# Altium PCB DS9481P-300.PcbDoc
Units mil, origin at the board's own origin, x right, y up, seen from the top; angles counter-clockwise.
Board outline 866.14 x 629.92 mil, 2 copper layers (Top Layer, Bottom Layer); 44 components, 31 nets, 174 pads, 34 vias.
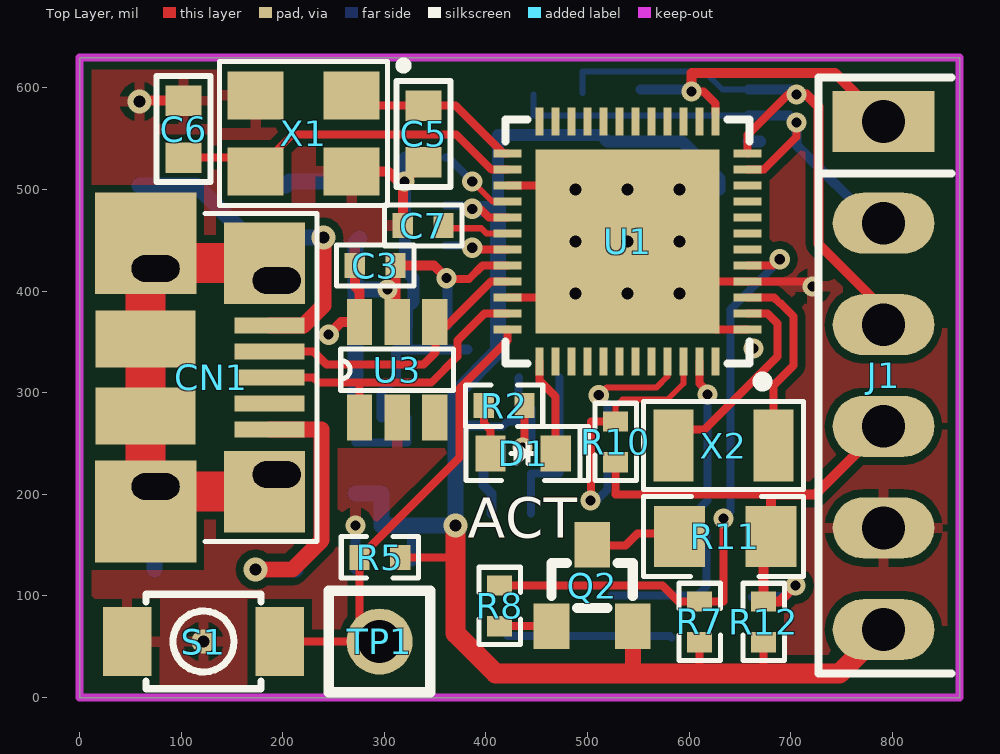
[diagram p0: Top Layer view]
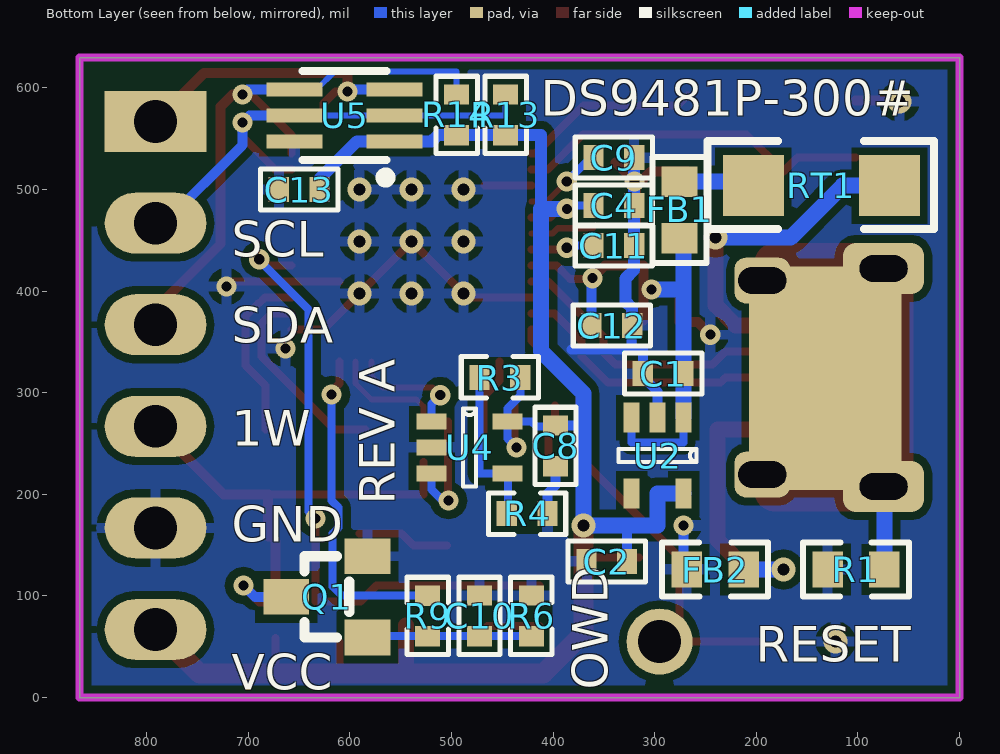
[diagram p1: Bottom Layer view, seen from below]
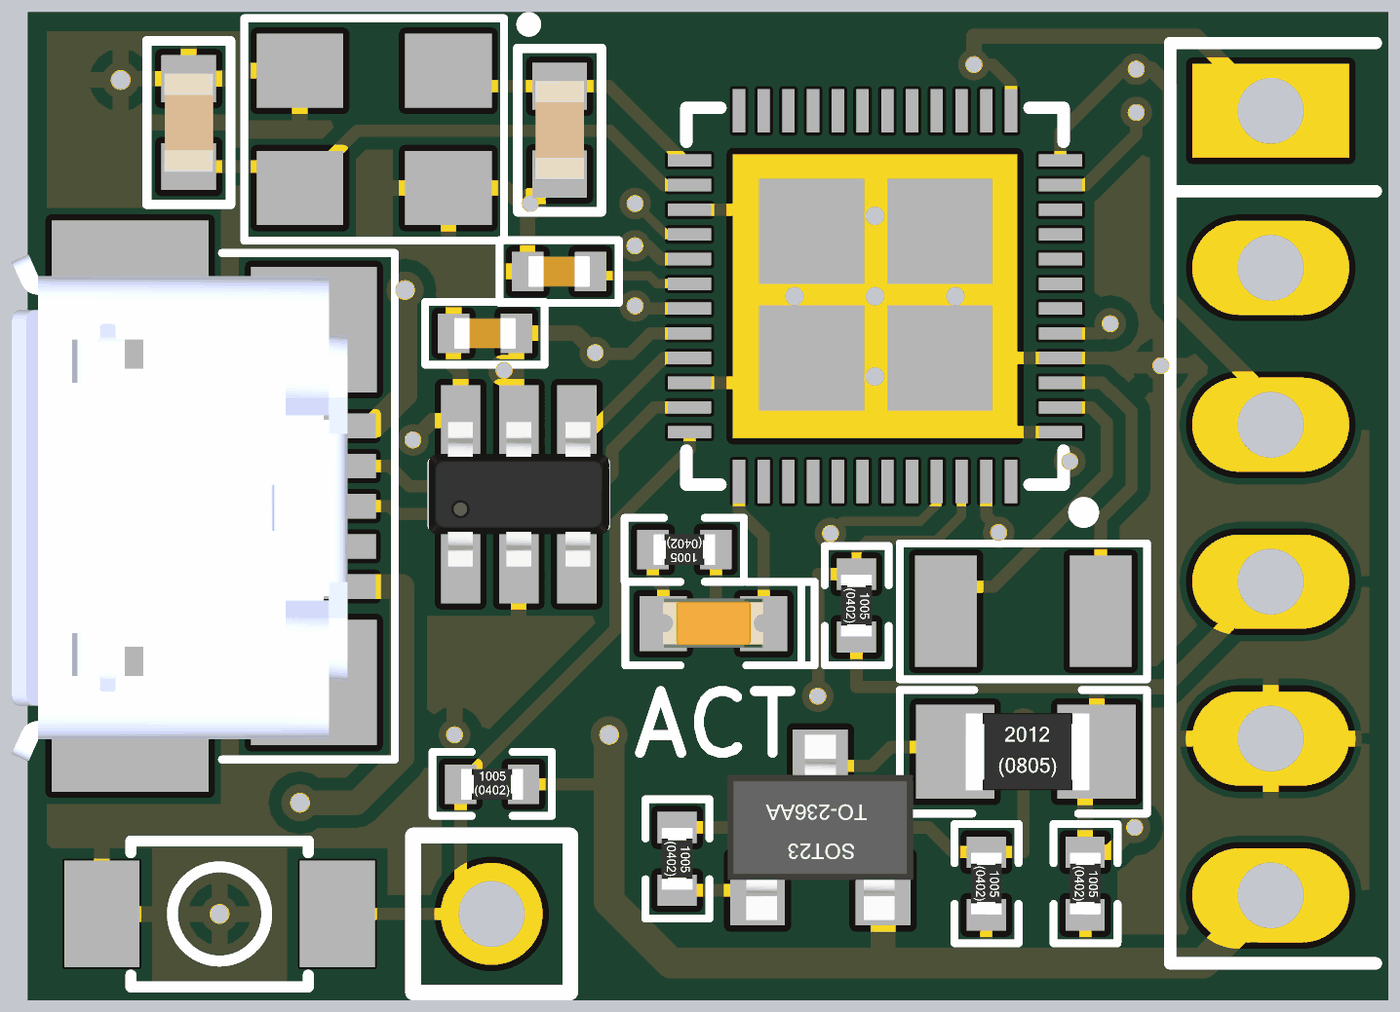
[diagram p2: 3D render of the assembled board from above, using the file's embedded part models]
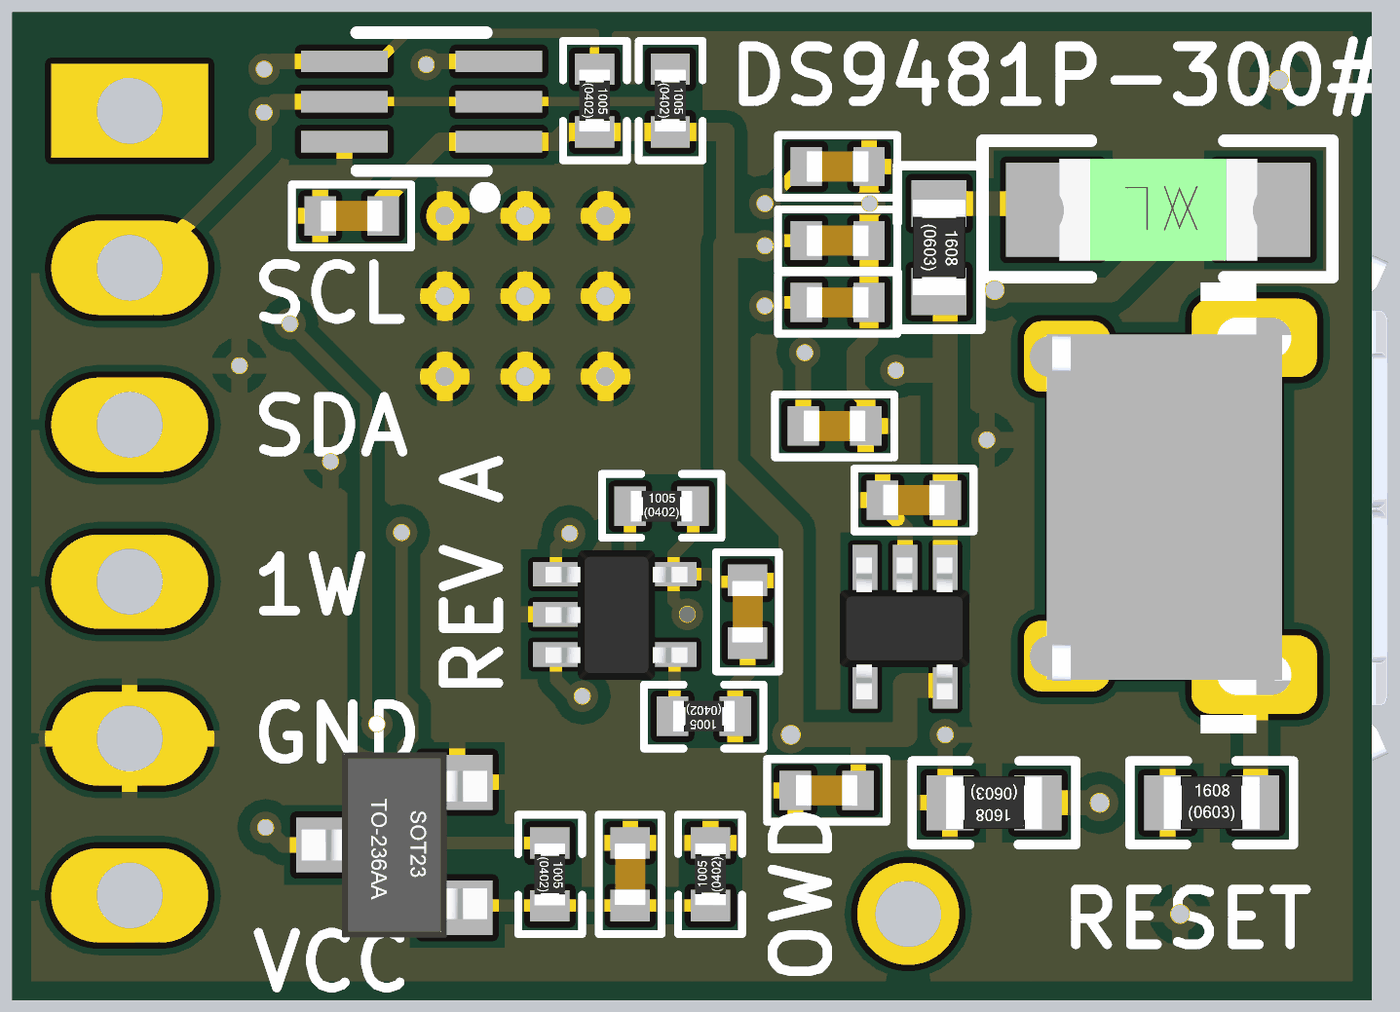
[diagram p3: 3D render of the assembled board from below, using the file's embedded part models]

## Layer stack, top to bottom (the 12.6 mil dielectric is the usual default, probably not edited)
Top Layer: signal copper 1.4
Dielectric: dielectric 12.6, FR-4, Dk 4.8
Bottom Layer: signal copper 1.4

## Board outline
0,0 866.14,0 866.14,629.92 0,629.92

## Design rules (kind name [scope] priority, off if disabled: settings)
Clearance PolygonClearance [InPolygon] p1: gap=7.87
Clearance [All] p2: gap=6
DiffPairsRouting [All] p1: maxlimit=10 minlimit=10 mostfreqgap=10 maxuncoupledlength=500
HoleToHoleClearance [All] p1: gap=7.87 allowstackedmicrovias=TRUE
MinimumAnnularRing [All] p1: minimumring=5
MinimumSolderMaskSliver [All] p1: minsoldermaskwidth=3
PolygonConnect [All] p1: connectstyle=Relief reliefconductorwidth=10 reliefentries=4 polygonreliefangle="90 Angle"
RoomDefinition DS9481P-300 [InComponentClass('DS9481P-300')] p1: confinementstyle=ConfineIn formatcopy=TRUE lockcomponents=FALSE outline -114.17,-94.49 976.38,-94.49 976.38,724.41 -114.17,724.41
RoutingVias [All] p1: holewidth=11.81 width=23.62 viastyle="Through Hole" minholewidth=10 minwidth=20.08 maxholewidth=28 maxwidth=50
SilkToSilkClearance [All] p1: silktosilkclearance=5
SilkscreenOverComponentPads [All] p1: minsilkscreentomaskgap=4
SolderMaskExpansion [All] p1: expansion=4
Width POWER_NETS_Width [InNetClass('POWER_NETS')] p1: maxlimit=39.37 minlimit=7.87 preferedwidth=19.68
Width [All] p2: maxlimit=39.37 minlimit=6 preferedwidth=7.87
23 further rules are at their usual default settings.

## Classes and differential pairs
net class POWER_NETS: VCC3.3 VCC5.0
differential pair USB: +USB_P -USB_N

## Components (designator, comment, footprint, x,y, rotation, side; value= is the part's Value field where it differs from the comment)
C1 "1uF" CAP0402-3D 271.65,318.9 r0 bottom
C2 "1uF" CAP0402-3D 327.2,133.87 r0 bottom
C3 "0.1uF" CAP0402-3D 311.02,425.2 r180 top
C4 "1uF" CAP0402-3D 360.24,484.25 r180 bottom
C5 "10pF" CAP0603-3D 338.58,582.68 r270 top
C6 "10pF" CAP0603-3D 102.36,531.5 r90 top
C7 "1uF" CAP0402-3D 358.27,464.57 r180 top
C8 "0.1uF" CAP0402-3D 397.64,267.72 r270 bottom
C9 "1uF" CAP0402-3D 360.24,531.5 r180 bottom
C10 "10pF" CAP0402-3D 472.44,100.39 r270 bottom
C11 "1uF" CAP0402-3D 360.24,444.88 r180 bottom
C12 "1uF" CAP0402-3D 362.2,366.14 r180 bottom
C13 "0.1uF" CAP0402-3D 629.92,500 r0 bottom
CN1 "USB Micro B" USBMICROB-3D 7.87,314.96 r270 top
D1 "ACT" 0603LED-3DORANGE 468.5,240.16 r180 top
FB1 "" 0603-3D 275.59,507.87 r270 bottom
FB2 "" 0603-3D 212.6,125.98 r0 bottom
J1 "PMOD Output" SIP6-SOCKET2-RA-3D 791.34,566.93 r270 top
Q1 "2N7002" 16001-3D 582.68,59.06 r270 bottom
Q2 "PMV65XP" 16001-3D 464.57,70.24 r180 top
R1 "10" 0603-3D 129.92,125.98 r180 bottom
R2 "1.5k" 0402-3D 437.99,287.4 r180 top
R3 "100K" 0402-3D 472.44,314.96 r180 bottom
R4 "32.4K/1%" 0402-3D 405.51,181.1 r0 bottom
R5 "4.7k" 0402-3D 275.59,137.8 r0 top
R6 "100k" 0402-3D 421.26,100.39 r270 bottom
R7 "100k" 0402-3D 610.24,94.49 r270 top
R8 "1k" 0402-3D 413.39,110.24 r270 top
R9 "2.2k" 0402-3D 523.62,60.31 r90 bottom
R10 "499" 0402-3D 527.56,271.65 r270 top
R11 "4.99" 0805-3D 590.55,158.46 r0 top
R12 "680" 0402-3D 673.23,94.49 r270 top
R13 "1.74k" 0402-3D 446.85,593.5 r270 bottom
R14 "1.74k" 0402-3D 495.08,593.5 r270 bottom
RT1 "PTC Fuse MF-NSMF012-2" 1206POLYFUSE-3D 68.9,503.94 r0 bottom
S1 "RESET" RESET9-3d 122.05,55.12 r0 top
TP1 "OWD" SIP1 295.28,55.12 r180 top
U1 "MAXQ1010-A01+" "TQFN48 6MM" 539.37,448.82 r180 top
U2 "MAX8891" SC70-5-3D 271.65,275.59 r270 bottom
U3 "MAX3207" sot23-6-3D 275.59,275.59 r90 top
U4 "MAX9140" SC70-5-3D 519.69,271.65 r180 bottom
U5 "MAX13204E" "TDFN6 2MM .65" 552.17,547.24 r0 bottom
X1 "12 MHz Crystal" FA-238V 220.47,555.12 r180 top
X2 "DNP" M8 633.86,248.03 r180 top

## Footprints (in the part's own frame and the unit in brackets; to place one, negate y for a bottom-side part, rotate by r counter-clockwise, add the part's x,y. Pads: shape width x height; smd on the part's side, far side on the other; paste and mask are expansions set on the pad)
0402-3D [mil]
  rect 20x25 smd: 1(0,0) 2(40,0)
  silkscreen extent -18,-20 58,21, body extent 0,-10 40,10, height 14
0603-3D [mil]
  rect 30x35 smd: 1(0,0) 2(56,0)
  silkscreen extent -24,-27 80,27, body extent -3,-17 59,17, height 18
0603LED-3DORANGE [mil]
  rect 30x35 smd: 1(0,0) 2(64,0)
  silkscreen extent -32,-27 88,27, body extent 0,-16 64,15, height 24
0805-3D [mil]
  rect 50x60 smd: 1(0,0) 2(90,0)
  silkscreen extent -35,-39 122,39, body extent 7,-25 85,25, height 18
1206POLYFUSE-3D [mil]
  rect 60x60 smd: 1(0,0) 2(134,0)
  silkscreen extent -44,-44 179,43, body extent 4,-33 130,33, height 22
16001-3D [mil]
  rect 35x45 smd: 1(0,0) 2(-80,0) 3(-40,-80)
  silkscreen extent -80,-62 0,-18, body extent -99,-99 19,19, height 51
CAP0402-3D [mil]
  rect 20x25 smd: 1(0,0) 2(40,0)
  silkscreen extent -18,-20 58,20, body extent 0,-10 40,10, height 23
CAP0603-3D [mil]
  rect 30x35 smd: 1(0,0) 2(56,0)
  silkscreen extent -24,-27 80,27, body extent -3,-16 59,16, height 31
FA-238V [mm] "Seiko Epson FA-238V Crystal"
  rect 1.4x1.2 smd paste+0: 1(-1.2,-0.95)
  rect 1.4x1.2 smd: 2(1.2,-0.95) 3(1.2,0.95) 4(-1.2,0.95)
  silkscreen extent -2.1,-1.8 2.1,1.8, body extent -1.6,-1.25 1.6,1.25, height 0.7
M8 [mm] "Hong Kong X'tals M8 Crystal"
  rect 1x1.8 smd: 1(-1.25,0) 2(1.25,0)
  silkscreen extent -2,-1.1 2,1.1
RESET9-3d [mil]
  rect 48x68 smd mask+1.18: 1(-75,0) 2(75,0)
  silkscreen extent -57,-47 56,46, body extent -80,-50 80,50, height 66
SC70-5-3D [mm]
  rect 0.75x0.4 smd mask+0.076: 1(0,0) 2(0,-0.65) 3(0,-1.3) 4(1.9,-1.3) 5(1.9,0)
  silkscreen extent 0.79,-1.62 1.11,0.33, body extent -0.17,-1.71 2.13,0.39, height 1
SIP1 [mil]
  round 65 hole 42: 1(0,0)
  silkscreen extent -50,-50 50,50
SIP6-SOCKET2-RA-3D [mil]
  rect 60x100 hole 42: 1(0,0)
  oval 60x100 hole 42: 2(100,0) 3(200,0) 4(300,0) 5(400,0) 6(500,0)
  body extent -51,-12 551,169, height 100
sot23-6-3D [mil]
  rect 45x25 smd: 1(0,0) 2(0,-37) 3(0,-74) 4(94,-74) 5(94,-37) 6(94,0)
  silkscreen extent 26,-92 68,19, body extent 1,-94 93,20, height 39
"TDFN6 2MM .65" [mm]
  rect 1.4x0.35 smd: 1(0.1,0) 2(0.1,-0.65) 3(0.1,-1.3) 4(2.6,-1.3) 5(2.6,-0.65) 6(2.6,0)
  silkscreen extent 0.2,-1.77 2.4,1.02, body extent 0.33,-1.67 2.37,0.38, height 0.8
"TQFN48 6MM" [mm] "48Pin 6x6mm Body 0.4mm pitch"
  rect 0.7x0.2 smd mask+0.051: 1(-3,2.2) 2(-3,1.8) 3(-3,1.4) 4(-3,1) 5(-3,0.6) 6(-3,0.2) 7(-3,-0.2) 8(-3,-0.6) 9(-3,-1) 10(-3,-1.4) 11(-3,-1.8) 12(-3,-2.2) 25(3,-2.2) 26(3,-1.8) 27(3,-1.4) 28(3,-1) 29(3,-0.6) 30(3,-0.2) 31(3,0.2) 32(3,0.6) 33(3,1) 34(3,1.4) 35(3,1.8) 36(3,2.2)
  rect 0.2x0.7 smd mask+0.051: 13(-2.2,-3) 14(-1.8,-3) 15(-1.4,-3) 16(-1,-3) 17(-0.6,-3) 18(-0.2,-3) 19(0.2,-3) 20(0.6,-3) 21(1,-3) 22(1.4,-3) 23(1.8,-3) 24(2.2,-3) 37(2.2,3) 38(1.8,3) 39(1.4,3) 40(1,3) 41(0.6,3) 42(0.2,3) 43(-0.2,3) 44(-0.6,3) 45(-1,3) 46(-1.4,3) 47(-1.8,3) 48(-2.2,3)
  rect 4.6x4.6 smd paste-5: EP(0,0)
  silkscreen extent -3.5,-3.05 3.05,3.62, body extent -3.05,-3.05 3.05,3.05, height 0.8
USBMICROB-3D [mm]
  rect 0.4x1.75 smd mask+0.076: 1(-1.3,4.555) 2(-0.65,4.555) 3(0,4.555) 4(0.65,4.555) 5(1.3,4.555)
  rrect50% 1.143x1.397 hole 0.66 slot 1.2 at 90 deg: 6(2.425,4.73) 9(-2.425,4.73)
  rrect50% 1.27x2.032 hole 0.66 slot 1.2 at 90 deg: 7(2.725,1.7) 8(-2.725,1.7)
  rect 2.032x2.032 smd: 10(-2.86,4.425) 11(2.855,4.425)
  rect 2.54x2.54 smd: 12(3.35,1.453) 15(-3.355,1.453)
  rect 1.43x2.5 smd: 13(0.96,1.45) 14(-0.96,1.45)
  rect 5.588x3.81 smd far side mask+0.03: 16(0.013,3.155)
  silkscreen extent -4.1,2.94 4.1,5.73, body extent -4.07,-0.46 4.13,4.97, height 2.62

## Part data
C1 C2 C4 C7 C9 C11 C12: library part CAP, "CAP CER 1UF 6.3V 20% X5R 0402"
C3 C8 C13: library part CAP, "CAP CER 0.1UF 6.3V 10% X5R 0402"
C5 C6: library part CAP, "CAP CER 10PF 50V C0G 0603"
C10: library part CAP, "CAP CER 10PF 50V 5% NP0 0402"
CN1: library part USB-MICRO-B, "CONN RCPT STD MICRO USB TYPE B"
D1: library part LED, "LED ORANGE HIGH BRIGHT USS 0603"
FB1 FB2: library part FUSE1, "FERRITE CHIP 220 OHM 2200MA 0603"
J1: library part CON6, "CONN RCPT .100\" 6POS R/A SGL TIN"
Q1: library part "NCHAN FET", "N MOSFET - 2N7002"
Q2: library part "PCHAN FET", "P-MOSFET - PMV65XP"
R1: library part RESISTOR, "RES SMD 10 OHM 5% 1/10W 0603"
R2: library part RESISTOR, "RES SMD 1.5K OHM 5% 1/16W 0402"
R3 R6 R7: library part RESISTOR, "RES SMD 100K OHM 1% 1/16W 0402"
R4: library part RESISTOR, "RES SMD 32.4K OHM 1% 1/16W 0402"
R5: library part RESISTOR, "RES SMD 4.7K OHM 5% 1/10W 0402"
R8: library part RESISTOR, "RES SMD 1K OHM 5% 1/16W 0402"
R9: library part RESISTOR, "RES SMD 2.2K OHM 5% 1/10W 0402"
R10: library part RESISTOR, "RES SMD 499 OHM 1% 1/16W 0402"
R11: library part RESISTOR, "RES SMD 4.99 OHM 1% 1/8W 0805"
R12: library part RESISTOR, "RES SMD 680 OHM 5% 1/10W 0402"
R13 R14: library part RESISTOR, "RES SMD 1.74K OHM 1% 1/10W 0402"
RT1: library part THERMISTOR, "PTC Fuse 1206"
S1: library part SW-PB, "SWITCH TACTILE SPST-NO 0.05A 12V"
TP1: library part TP, "CONN HEADER 1POS .100 VERT GOLD"
U1: library part MAXQ1010, "Security Token Microcontroller with RTC and USB"
U2: "High PSRR, Low-Dropout, 150mA  Linear Regulator"
U3: library part MAX3207E, "Dual High-Speed  Differential ESD-Protection IC"
U4: library part OPAMP, "40ns Single-Supply Comparator"
U5: library part MAX13204, "4 Channel +/- 30kv ESD Protector"
X1: library part CRYSTAL3, "CRYSTAL 12MHZ 10PF SMD"
X2: library part CRYSTAL, "Do Not Populate"

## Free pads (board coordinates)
  round 10 hole 10 mask+0: 2(2240.16,19.68)
  round 11.81 hole 11.81 mask+0: 5(2240.16,-141.73)
  round 0 hole 25.98 slot 47.24 at 0 deg mask+0: ""(2240.16,-456.69)
  round 42 hole 42 mask+0: ""(2240.16,-295.28)

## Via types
v1: diameter 20.08, hole 10, Top Layer to Bottom Layer, tented both sides, 20 vias
v2: diameter 23.62, hole 11.81, Top Layer to Bottom Layer, 9 vias
v3: diameter 23.62, hole 11.81, Top Layer to Bottom Layer, tented both sides, 5 vias

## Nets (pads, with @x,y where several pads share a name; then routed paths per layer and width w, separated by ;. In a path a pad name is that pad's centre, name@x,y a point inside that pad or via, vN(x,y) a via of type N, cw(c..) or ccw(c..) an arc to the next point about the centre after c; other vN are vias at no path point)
1-WIRE: J1.4 Q1.3 R10.2 R11.2 R12.1 | length 519
  Top Layer w7.87: R10.2 527.56,199.8 680.12,199.8
  Top Layer w9.84: 680.12,199.8 724.21,199.8 J1.4 ; R11.2 R11.2@680.55,161.42 ; 680.55,199.37 R11.2@680.55,161.42 ; v1(704.72,110.24) 688.98,94.49 R12.1 673.23,154.09 R11.2@680.55,161.42
  Bottom Layer w9.84: Q1.3 693.54,99.06 v1(704.72,110.24)
1-WIRE_DRIVE: R9.2 U1.47 | length 327
  Top Layer w7.87: U1.47 610.24,309.06 618.11,301.18 v1(618.11,298.23)
  Bottom Layer w7.87: R9.2 608.05,100.31 616.99,109.25 616.99,161.56 611.22,167.32 611.22,187.01 618.11,193.9 v1(618.11,298.23)
1-WIRE_SENSE: R10.1 U1.46 U4.3 | length 252.7
  Top Layer w6: R10.1 527.56,286.42 534.45,293.31 578.74,293.31 594.49,309.06 U1.46
  Top Layer w7.87: v1@503.25,192.91 503.25,271.65 R10.1
  Bottom Layer w7.87: v1(502.95,193.9) 508.86,193.9 519.69,204.73 U4.3
EDGE_DET: U1.45 U4.1 | length 119.5
  Top Layer w6: v1(511.06,297.62) 518.74,305.31 568.03,305.31 578.74,316.01 U1.45
  Bottom Layer w7.87: v1(511.06,297.62) 519.69,288.99 U4.1
GND: C1.2 C2.2 C3.2 C4.2 C5.2 C6.2 C7.2 C8.2 C9.2 C10.1 C11.2 C12.2 C13.2 FB2.2 J1.5 Q1.2 R1.1 R4.1 R6.1 S1.1 U1.1 U1.4 U1.27 U1.34 U1.EP U2.2 U3.2 U3.6 U4.2 U5.6 X1.2 X1.4 | length 1166.4
  Top Layer w7.87: U1.34 484.25,393.7 v2(488.19,397.64) v2(539.37,448.82) v2(590.55,397.64) 625.98,362.2 U1.1 ; U1.27 U1.EP@467.52,503.94 ; U1.EP@484.33,504.01 U1.EP@488.19,507.87 ; U1.EP@610.24,409.45 U1.4 690.21,409.45 716.54,409.45 v1(721.46,404.53) v1@721.46,404.59
  Top Layer w9.84: v3@59.06,587.5 C6.2 ; v1(245.16,357.2) 257.54,369.59 U3.6 275.59,399.96 271.02,404.53 C3.2 ; X1.4 303.86,517.72 v1@318.27,503.31 ; C7.2 v1@318.27,503.31 ; C5.2 318.9,506.99 318.9,503.94 v1@318.27,503.31
  Bottom Layer w9.84: FB2.2@271.65,125.98 v1(271.65,169.29) ; U2.2 297.24,301.18 311.65,315.59 C1.2 311.65,342.52 322.83,342.52 ; C12.2@322.83,366.14 322.83,342.52 ; 381.89,342.52 322.83,342.52 ; C8.2 397.64,208.66 405.51,200.79 R4.1
  Bottom Layer w11.81: C9.2 C4.2 C11.2 320.24,420.91 328.74,412.4 328.74,389.76 322.2,383.23 C12.2 ; U5.6@658.46,547.24 U5.6@669.92,547.24
  other v1: 663.39,343.5 319.88,507.87
  other v2: 539.37,397.64 488.19,448.82 590.55,448.82 488.19,500 539.37,500 590.55,500
  other v3: 122.05,55.12 59.06,586.61
GND_EARTH: CN1.6 CN1.7 CN1.8 CN1.9 CN1.10 CN1.11 CN1.12 CN1.13 CN1.14 CN1.15 CN1.16 R1.2 | length 535.5
  Top Layer w39.37: CN1.11 70.19,202.56 65.07,207.68 65.07,352.76 65.07,422.24 70.39,427.56 CN1.10
  Bottom Layer w15.75: R1.2 73.92,207.68 CN1.7
GPIO: J1.1 U1.13 U5.3 | length 316.1
  Top Layer w7.87: v1(602.36,596.46) 614.17,596.46 625.98,584.65 U1.13@625.98,574.8
  Top Layer w9.84: v1(602.36,596.46) 602.36,614.5 743.77,614.5 J1.1
  Bottom Layer w7.87: v1@600.39,598.43 v1(602.36,596.46)
  Bottom Layer w9.84: U5.3@552.17,598.43 v1@600.39,598.43
N_1-WIRE_DPU: R7.1 R8.1 U1.5 | length 621.9
  Top Layer w7.87: R8.1 573.71,110.24 589.46,94.49 633.86,94.49 v1(633.86,176.18) ; U1.5 683.07,425.2 v1(689.17,431.3)
  Bottom Layer w7.87: v1(633.86,176.18) 640.75,183.07 640.75,381.89 689.96,431.1 689.37,431.1 v1(689.17,431.3)
NetC5_1: C5.1 U1.25 X1.1 | length 177.2
  Top Layer w7.87: X1.1 277.56,582.68 C5.1 370.08,582.68 417.36,535.4 U1.25
NetC6_1: C6.1 U1.26 X1.3 | length 354.2
  Top Layer w7.87: C6.1 159.45,531.5 X1.3 209.88,554.37 370.5,554.37 405.37,519.5 U1.26@421.26,519.5
NetC7_1: C7.1 U1.30 | length 66.2
  Top Layer w6: C7.1 360.98,461.85 395.38,461.85 400.41,456.82 U1.30@421.26,456.82
NetC9_1: C9.1 U1.28 | length 79
  Top Layer w6: v1(386.61,507.87) 406.3,488.19 U1.28
  Bottom Layer w7.87: C9.1 362.99,531.5 v1(386.61,507.87)
NetC10_2: C10.2 Q1.1 R6.2 R9.1 | length 162
  Bottom Layer w7.87: R6.2 523.62,60.39 581.34,60.39 Q1.1
NetC11_1: C11.1 U1.31 | length 62.7
  Top Layer w7.87: v1(386.61,442.61) 388.28,440.94 U1.31
  Bottom Layer w7.87: C11.1 384.35,444.88 v1(386.61,442.61)
NetCN1_1: CN1.1 RT1.1 | length 330.2
  Top Layer w15.75: CN1.1 220.28,366.14 240.16,386.02 v3(240.16,452.76)
  Bottom Layer w15.75: RT1.1@59.06,503.94 115.16,503.94 166.34,452.76 v3(240.16,452.76)
NetCN1_5: CN1.5 FB2.1 | length 276.2
  Top Layer w15.75: v3(173.23,125.98) 209.31,125.98 238.19,154.87 238.19,263.78 CN1.5
  Bottom Layer w15.75: v3(173.23,125.98) FB2.1
NetD1_1: D1.1 U1.37 | length 97.1
  Top Layer w7.87: U1.37 452.76,312.01 468.5,296.26 D1.1
NetD1_2: D1.2 R2.2 | length 49.9
  Top Layer w7.87: R2.2 397.99,269.86 404.5,263.35 D1.2
NetFB1_1: FB1.1 RT1.2 | length 74.3
  Bottom Layer w15.75: RT1.2 206.83,507.87 FB1.1
NetQ2_1: Q2.1 R8.2 | length 51.2
  Top Layer w7.87: R8.2 Q2.1
NetQ2_3: Q2.3 R11.1 | length 90.9
  Top Layer w7.87: Q2.3@504.57,149.61 537.48,149.61 549.29,161.42 R11.1@590.55,161.42
NetR3_1: R3.1 R4.2 U4.4 | length 162
  Bottom Layer w7.87: R4.2@444.25,181.1 444.25,220.47 U4.4 472.44,220.47 R3.1
NetU1_2: U1.2 X2.2 | length 198.2
  Top Layer w7.87: X2.2@584.65,263.78 615.16,263.78 687.01,335.63 687.01,368.11 677.17,377.95 U1.2
NetU1_3: U1.3 X2.1 | length 172.5
  Top Layer w7.87: U1.3 683.69,393.7 689.79,387.6 690.36,387.6 702.76,375.2 702.76,326.77 683.07,307.09 X2.1@683.07,263.78
OWD_NRST: R5.1 S1.2 TP1.1 U1.36 | length 490.5
  Top Layer w7.87: S1.2 TP1.1 ; TP1.1@307.09,66.93 TP1.1 ; U1.36 421.26,351.4 374.02,304.15 374.02,236.22 R5.1 275.59,74.8 TP1.1
SCL: J1.2 R13.1 U1.11 U5.2 U5.5 | length 499.3
  Top Layer w7.87: U1.11@657.63,519.83 U1.11 673.5,519.69 705.71,551.89 v1(705.71,565.94)
  Bottom Layer w6: R13.1 446.85,572.83 552.17,572.83 U5.5@658.46,572.83
  Bottom Layer w7.87: v1@704.72,564.96 v1(705.71,565.94)
  Bottom Layer w9.84: U5.5@658.46,572.83 698.82,572.83 v1(705.71,565.94) 705.71,543.65 782.43,466.93 J1.2
SDA: J1.3 R14.1 U1.12 U5.4 | length 592.1
  Top Layer w7.87: U1.12 657.48,553.52 697.46,593.5 v1(705.71,593.5)
  Top Layer w9.84: v1(705.71,593.5) 715.35,593.5 727.36,581.5 727.36,446.49 791.34,382.51 J1.3
  Bottom Layer w6: R14.1@495.08,594.84 495.08,616.28 615.02,616.28 632.87,598.43 U5.4@658.46,598.43
  Bottom Layer w9.84: U5.4@658.46,598.43 700.79,598.43 v1(705.71,593.5)
USB_N: CN1.2 U1.33 U3.4 | length 282.2
  Top Layer w7.87: CN1.2 230.31,340.55 243.09,327.78 338.69,327.78 350.39,339.48 350.39,354.88 404.96,409.45 U1.33
USB_P: CN1.3 U1.35 U3.1 | length 307.7
  Top Layer w7.87: CN1.3 230.32,314.96 235.37,309.9 275.59,309.9 ; U3.1 275.59,309.9 ; U1.35 398.74,377.95 372.05,351.26 372.05,335.82 346.13,309.9 275.59,309.9
VCC3.3: C2.1 C4.1 C8.1 C13.1 J1.6 Q2.2 R2.1 R3.2 R5.2 R7.2 R12.2 R13.2 R14.2 U1.29 U2.5 U4.5 U5.1 | length 1829.6
  Top Layer w7.87: R5.2 370.08,137.8 ; v1(386.47,480.95) 394.58,480.95 403.09,472.44 U1.29 ; v1(436.02,246.06) 437.99,248.03 R2.1 ; 610.24,23.84 R7.2 ; 673.23,23.84 R12.2 R12.2@673.23,58.43
  Top Layer w15.75: 544.57,23.84 Q2.2 Q2.2@544.57,70.87
  Top Layer w19.68: v3(370.08,169.29) 370.08,137.8 370.08,63.21 409.45,23.84 544.57,23.84 610.24,23.84 673.23,23.84 748.25,23.84 J1.6
  Bottom Layer w7.87: C4.1 383.17,484.25 v1(386.47,480.95) ; v3@362.2,169.29 v3(370.08,169.29) ; C8.1 398.43,266.93 416.53,266.93 421.26,271.65 U4.5 ; R3.2 432.09,314.61 432.09,297.24 444.88,284.45 U4.5 ; v1(436.02,246.06) 444.88,254.92 U4.5
  Bottom Layer w9.84: C2.1 327.2,169.29 ; 370.08,267.72 C8.1
  Bottom Layer w11.81: 411.71,480.95 411.71,553.5 R13.2 R14.2 513.43,553.5 519.68,547.24 U5.1 593.23,547.24 629.92,510.55 C13.1
  Bottom Layer w15.75: U2.5 297.24,200.79 297.24,169.29 326.77,169.29 ; 327.2,169.29 v3@362.2,169.29 ; v3(370.08,169.29) 370.08,267.72 370.08,299.21 411.71,340.84 411.71,480.95 v1(386.47,480.95)
VCC5.0: C1.1 C3.1 C12.1 FB1.2 U1.32 U2.1 U2.3 U3.5 | length 542.2
  Top Layer w7.87: U3.5@311.02,371.16 U3.5 ; v1@361.9,412.16 383.56,412.16 396.54,425.14 U1.32@421.26,425.14
  Top Layer w9.84: v1(303.15,401.57) v1@311.02,401.57 ; U3.5@311.02,371.16 v1@311.02,401.57 ; v1@361.9,412.16 v1(361.22,412.84) 348.86,425.2 C3.1 v1@311.02,401.57
  Bottom Layer w7.87: U2.1 271.65,250.89 322.83,250.89 U2.3
  Bottom Layer w9.84: v1(361.22,412.84) 362.2,411.85 C12.1
  Bottom Layer w15.75: U2.1 C1.1 271.65,401.57 ; FB1.2 271.65,447.94 271.65,401.57 ; v1(303.15,401.57) 271.65,401.57
pads on no net: CN1.4 U1.6 U1.7 U1.8 U1.9 U1.10 U1.14 U1.15 U1.16 U1.17 U1.18 U1.19 U1.20 U1.21 U1.22 U1.23 U1.24 U1.38 U1.39 U1.40 U1.41 U1.42 U1.43 U1.44 U1.48 U2.4 U3.3

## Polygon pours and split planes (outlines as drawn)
GND on Bottom Layer "Bottom Layer GND" (solid, remove dead copper, pour order 6): 0,0 866.14,0 866.14,629.92 0,629.92
GND on Top Layer "Top Layer GND" (solid, remove dead copper, pour order 5): 0,0 866.14,0 866.14,629.92 0,629.92

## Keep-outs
Keep-Out Layer:
  the board outline again, w7.87

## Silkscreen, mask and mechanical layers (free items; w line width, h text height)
Top Overlay:
  circle w7.87: c318.9,622.05 r3.94
  lines w7.87: 727.36,515.75 858.27,515.75 ; 858.27,23.62 727.36,23.62 727.36,610.24 858.27,610.24
Bottom Overlay:
  text "DS9481P-300#" at 412.4,572.83 h35
  text "SCL" at 716.46,434.06 h35
  text "SDA" at 716.46,349.41 h35
  text "1W" at 716.54,248.03 h35
  text "REV A" at 556.1,189.96 h35 r270
  text "GND" at 716.54,153.54 h35
  text "VCC" at 716.54,7.87 h35
Top Paste:
  rectangle: 465.55,375.98 532.48,442.91
  rectangle: 465.55,456.69 532.48,523.62
  rectangle: 547.24,375.98 614.17,442.91
  rectangle: 547.24,456.69 614.17,523.62
Mechanical 15:
  circle w11.81: c275.59,322.83 r3.94
  circle w11.81: c657.48,346.46 r3.94
  lines w5: 720.47,515.75 858.27,515.75 ; 379.92,267.72 379.92,308.07 455.71,308.07 455.71,267.72 379.92,267.72 ; 379.92,267.72 492.13,267.72 ; 379.92,267.72 379.92,212.6 492.13,212.6 ; 492.13,212.6 492.13,267.72 ; 492.13,212.6 500.98,212.6 500.98,267.72 492.13,267.72 ; 7.87,153.54 232.28,153.54 232.28,476.38 7.87,476.38 7.87,153.54 ; 15.75,7.87 228.35,7.87 228.35,102.36 15.75,102.36 15.75,7.87 ; 74.8,507.87 129.92,507.87 129.92,610.24 74.8,610.24 74.8,507.87 ; 252.95,405.51 295.28,405.51 328.74,405.51 328.74,444.88 252.95,444.88 252.95,405.51 ; 255.91,118.11 334.65,118.11 334.65,157.48 255.91,157.48 255.91,118.11 ; 259.84,248.03 366.14,248.03 366.14,397.64 259.84,397.64 259.84,248.03 ; 300.39,444.88 375.98,444.88 375.98,484.25 300.39,484.25 300.39,444.88 ; 311.02,503.94 366.14,503.94 366.14,606.3 311.02,606.3 311.02,503.94 ; 393.7,51.18 433.07,51.18 433.07,129.92 393.7,129.92 393.7,51.18 ; 440.94,43.31 440.94,102.36 460.63,102.36 460.63,177.17 547.24,177.17 547.24,98.43 566.93,98.43 566.93,43.31 440.94,43.31 ; 507.87,212.6 547.24,212.6 547.24,291.34 507.87,291.34 507.87,212.6 ; 555.12,122.05 712.6,122.05 712.6,200.79 555.12,200.79 555.12,122.05 ; 590.55,35.43 629.92,35.43 629.92,114.17 590.55,114.17 590.55,35.43 ; 653.54,35.43 692.91,35.43 692.91,114.17 653.54,114.17 653.54,35.43 ; 720.47,23.62 862.2,23.62 862.2,610.24 720.47,610.24 720.47,23.62
  text "TOP ASSEMBLY" at -34.45,921.26 h80
  text "C6" at 118.11,535.43 h30 r90
  text "C5" at 354.33,531.5 h30 r90
  text "U1" at 519.68,500 h30
  text "C7" at 322.83,452.76 h25
  text "C3" at 270.67,412.84 h25
  text "U3" at 303.15,307.09 h30
  text "CN1" at 90.55,303.15 h30
  text "J1" at 775.59,303.15 h30
  text "R2" at 396.65,275.59 h25
  text "D1" at 417.32,228.35 h30
  text "R10" at 539.37,220.47 h25 r90
  text "R11" at 598.43,149.61 h30
  text "R5" at 275.59,125.98 h25
  text "Q2" at 480.32,94.49 h30
  text "R8" at 425.2,70.87 h25 r90
  text "R7" at 622.05,55.12 h25 r90
  text "R12" at 685.04,43.31 h25 r90
  text "S1" at 102.36,39.37 h30
Mechanical 16:
  circle w11.81: c583.66,545.9 r3.94
  circle w11.81: c267.72,237.2 r3.94
  circle w11.81: c482.28,271.65 r3.94
  lines w5: 302.17,429.13 302.17,425.2 377.95,425.2 377.95,464.57 ; 303.15,503.94 377.95,503.94 377.95,464.57 ; 412.3,295.28 491.04,295.28 ; 425.2,287.4 425.2,204.72 539.37,204.72 539.37,287.4 492.13,287.4 ; 24.61,547.24 248.03,547.24 ; 24.61,547.24 248.03,547.24 ; 24.61,547.24 24.61,460.63 248.03,460.63 248.03,547.24 ; 303.15,429.13 303.15,531.5 248.03,531.5 248.03,429.13 303.15,429.13 ; 303.15,429.13 303.15,464.57 377.95,464.57 ; 492.13,287.4 492.13,335.33 413.39,335.33 413.39,287.4 492.13,287.4 ; 51.18,98.43 153.54,98.43 153.54,153.54 51.18,153.54 51.18,98.43 ; 187.99,98.43 293.31,98.43 293.31,153.54 187.99,153.54 187.99,98.43 ; 251.97,182.09 251.97,294.29 342.52,294.29 342.52,182.09 251.97,182.09 ; 252.95,299.21 329.72,299.21 329.72,338.58 252.95,338.58 252.95,299.21 ; 303.15,511.81 377.95,511.81 377.95,551.18 303.15,551.18 303.15,511.81 ; 304.13,346.46 304.13,385.83 379.92,385.83 379.92,346.46 304.13,346.46 ; 309.06,113.19 385.83,113.19 385.83,153.54 309.06,153.54 309.06,113.19 ; 377.95,208.66 417.32,208.66 417.32,287.4 377.95,287.4 377.95,208.66 ; 385.83,161.42 464.57,161.42 464.57,200.79 385.83,200.79 385.83,161.42 ; 401.57,39.37 440.94,39.37 440.94,118.11 401.57,118.11 401.57,39.37 ; 426.18,535.43 426.18,612.2 466.54,612.2 466.54,535.43 426.18,535.43 ; 452.76,39.37 492.13,39.37 492.13,118.11 452.76,118.11 452.76,39.37 ; 474.41,535.43 474.41,612.2 514.76,612.2 514.76,535.43 474.41,535.43 ; 503.94,39.37 543.31,39.37 543.31,43.31 543.31,118.11 503.94,118.11 503.94,39.37 ; 521.65,528.54 521.65,617.13 689.96,617.13 689.96,528.54 521.65,528.54 ; 555.12,35.43 610.24,35.43 610.24,59.06 688.98,59.06 688.98,137.8 610.24,137.8 610.24,161.42 555.12,161.42 555.12,35.43 ; 612.2,480.32 612.2,519.86 687.99,519.86 687.99,480.32 612.2,480.32
  text "U5" at 677.17,560.04 h25
  text "R14" at 482.28,543.31 h25 r270
  text "R13" at 434.06,542.32 h25 r270
  text "C9" at 362.2,518.7 h25
  text "RT1" at 161.42,492.13 h30
  text "C13" at 681.1,488.19 h25
  text "C4" at 361.22,472.44 h25
  text "FB1" at 259.84,444.88 h30 r270
  text "C11" at 367.13,432.09 h25
  text "C12" at 374.02,354.33 h25
  text "C1" at 308.07,306.1 h25
  text "R3" at 472.44,303.15 h25
  text "C8" at 385.83,228.35 h25 r270
  text "U4" at 503.94,224.41 h30
  text "U2" at 332.68,222.44 h30
  text "R4" at 444.88,169.29 h25
  text "C2" at 368.11,121.06 h25
  text "R1" at 122.05,110.24 h30
  text "FB2" at 280.51,110.24 h30
  text "Q1" at 637.8,86.61 h30
  text "R9" at 511.45,59.06 h25 r270
  text "R6" at 408.46,58.07 h25 r270
  text "C10" at 459.65,47.24 h25 r270
  text "BOTTOM ASSEMBLY" at 1051.18,-225.39 h80
Mechanical 31:
  drawing of 74 lines, arcs and shapes, not listed
  text "DS9481P-300#" at 2119.09,1035.43 h50
  text "Part Number: 89-9481P#300" at 1783.77,925.36 h50
  text "Notes:" at 3245.77,844.36 h50
  text "Property of" at 2022.77,820.36 h50
  text "Rev" at 2948.77,785.36 h50
  text "1. Material: RoHS Compliant FR-408 or similar laminate material" at 3245.77,760.36 h50
  text "2. Board Dimensions: 22 x 16 mm" at 3245.77,679.36 h50
  text "maxim" at 2199.36,675.94 h120
  text "A" at 3000.77,628.36 h50
  text "3. Board Thickness: 62 mil" at 3245.77,609.36 h50
  text "integrated" at 2199.36,577.94 h120
  text "TM" at 2678.77,569.36 h30
  text "4. Layers: 2 (Top, Bottom)" at 3245.77,539.36 h50
  text "5. Minimum Trace spacing / Trace width: 0.1524 mm / 0.1524 mm" at 3245.77,467.36 h50
  text "Drill and Mechanical Layer" at 1785.77,415.36 h50
  text "6. Copper Thickness: 1 oz on all layers" at 3245.77,392.36 h50
  text "Date: JUN 17 2015" at 1695.77,319.36 h50
  text "Units in mm" at 2530.77,317.36 h50
  text "7. Surface mount pads: 159" at 3245.77,317.36 h50
  text "8. Soldermask: GREEN" at 3245.77,242.36 h50
  text "9. Legend: white Top layer only" at 3245.77,176.36 h50
  text "SIZE" at 1726.77,121.36 h50
  text "QTY" at 1993.77,121.36 h50
  text "SYM" at 2171.77,121.36 h50
  text "PLATED" at 2366.77,121.36 h50
  text "TOLERANCE" at 2691.77,121.36 h50
  text "10. Plating: Best plating option for lead free" at 3245.77,100.36 h50
  text "11. Finish: Best finish option for lead free" at 3245.77,18.36 h50
  text "20" at 2013.78,-7.87 h50
  text "YES" at 2429.77,-7.64 h50
  text "0.254" at 1711.61,-10.83 h50
  text "0.005 in" at 2720.47,-12.8 h50
  text "12. Vendor Logo & date code: Allowed on bottom side only" at 3245.77,-58.64 h50
  text "13. Through holes: quantity 45, minimum size 0.254 mm" at 3245.77,-139.64 h50
  text "0.005 in" at 2722.44,-163.39 h50
  text "0.300" at 1705.71,-164.37 h50
  text "14" at 2015.75,-165.35 h50
  text "YES" at 2429.77,-165.64 h50
  text "14. Tolerances:" at 3245.77,-224.64 h50
  text "Plated-through holes +/- 0.005 in" at 3245.77,-303.64 h50
  text "0.005 in" at 2722.44,-316.93 h50
  text "7" at 2043.31,-318.9 h50
  text "YES" at 2433.71,-319.18 h50
  text "1.067" at 1708.66,-322.83 h50
  text "Pattern to pattern +/- 0.002 in" at 3245.77,-382.64 h50
  text "Legend to legend +/- no preference" at 3245.77,-464.64 h50
  text "0.660" at 1708.66,-476.38 h50
  text "4" at 2047.24,-484.25 h50
  text "YES" at 2440.94,-484.25 h50
  text "0.005 in" at 2724.41,-484.25 h50
  text "Soldermask to pattern +/- 0.002 in" at 3245.77,-543.64 h50
  text "15. Electrical testing needed" at 3253.77,-642.64 h50
  text "TOP METAL" at 1676.38,-1002.47 h70
  text "62 mil PCB" at 3368.38,-1033.47 h70
  text "Bottom Metal" at 4103.38,-1245.47 h70
  text "Bottom Metal" at 1679.38,-1253.47 h70

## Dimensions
944.88,0 to 944.88,629.92 on Mechanical 16
0,677.17 to 866.14,677.17 on Mechanical 16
